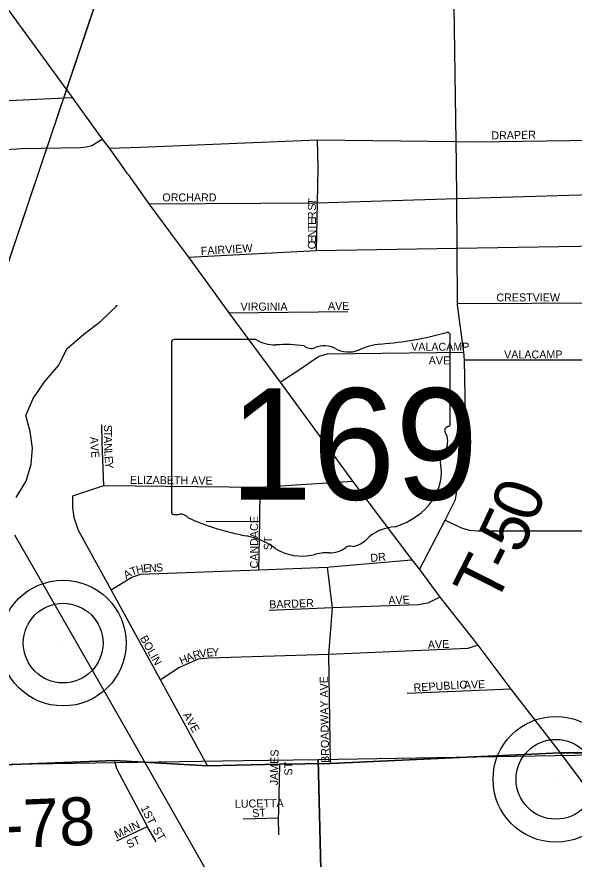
# Model space of a CAD drawing. Extents: x -37878.7 to -37844.7, y -19791.4 to -19769.4.
# Drawn here: x -37874.132 to -37873.473, y -19774.18 to -19773.183 of the extents above; entities that cross this region are included whole.
import ezdxf

# ---------------------------------------------------------------- set-up
doc = ezdxf.new("R2010")
doc.units = 0
for name, color, linetype in [('Default', 7, 'Continuous'), ('GM_X_City_Street', 7, 'Continuous'), ('GM_X_County_Road', 7, 'Continuous'), ('GM_X_County_Road_Text', 7, 'Continuous'), ('GM_X_Minor_River', 7, 'Continuous'), ('GM_X_Rail_Line', 7, 'Continuous'), ('GM_X_Section', 7, 'Continuous'), ('GM_X_State_Route', 7, 'Continuous'), ('GM_X_State_Shield', 7, 'Continuous'), ('GM_X_Township', 7, 'Continuous'), ('GM_X_Township_Road', 7, 'Continuous'), ('GM_X_Township_Road_Text', 7, 'Continuous'), ('GM_X_Township_Subdivision', 7, 'Continuous'), ('GM_X_Township_Subdivision_Text', 7, 'Continuous'), ('GM_X_Unincorporated', 7, 'Continuous'), ('TX_P_1', 7, 'Continuous')]:
    doc.layers.add(name, color=color, linetype=linetype)

msp = doc.modelspace()

# ---------------------------------------------------------------- linework, layer by layer
at = {"layer": 'Default'}
for p, q in [((-37874.07729, -19773.92383), (-37874.07729, -19773.92383)), ((-37873.49453, -19774.08503), (-37873.49453, -19774.08503))]:
    msp.add_line(p, q, dxfattribs=at)
at = {"layer": 'GM_X_City_Street'}
for points in [[(-37873.61204, -19773.35759), (-37873.61271, -19773.3304), (-37873.61542, -19773.1426), (-37873.61632, -19773.11857), (-37873.61725, -19773.09393), (-37873.61692, -19773.08252), (-37873.59457, -19773.0418), (-37873.58297, -19773.02513)], [(-37874.3297, -19773.21439), (-37874.32568, -19773.23387), (-37874.30662, -19773.27977), (-37874.30326, -19773.28503), (-37874.29938, -19773.28668), (-37874.29486, -19773.28661), (-37874.27396, -19773.2877), (-37874.26525, -19773.28737), (-37874.23344, -19773.28615), (-37874.205, -19773.2862), (-37874.14102, -19773.28178), (-37874.06671, -19773.27843)], [(-37874.205, -19773.2862), (-37874.20469, -19773.30441), (-37874.20247, -19773.32293), (-37874.20006, -19773.33471), (-37874.19902, -19773.33782), (-37874.19626, -19773.34058), (-37874.19282, -19773.34179), (-37874.18126, -19773.34224), (-37874.12653, -19773.33856), (-37874.05691, -19773.33742), (-37874.05005, -19773.33677), (-37874.04318, -19773.33497), (-37874.03126, -19773.32761)], [(-37874.02292, -19773.33824), (-37873.98583, -19773.3371), (-37873.77669, -19773.32839), (-37873.61271, -19773.3304), (-37873.58959, -19773.33068)], [(-37873.77568, -19773.36182), (-37873.77669, -19773.32839)]]:
    msp.add_lwpolyline(points, dxfattribs=at)
at = {"layer": 'GM_X_County_Road'}
for points in [[(-37873.48951, -19774.05375), (-37873.48951, -19774.05375), (-37873.43906, -19774.05375), (-37873.321, -19774.05101), (-37873.29591, -19774.0514), (-37873.22557, -19774.05028), (-37873.08696, -19774.04763), (-37873.07008, -19774.04829), (-37872.94239, -19774.04564), (-37872.88479, -19774.04389)], [(-37874.41791, -19774.07867), (-37874.01664, -19774.06271), (-37873.90676, -19774.06892), (-37873.82094, -19774.06728), (-37873.76132, -19774.06615), (-37873.48951, -19774.05375)]]:
    msp.add_lwpolyline(points, dxfattribs=at)
at = {"layer": 'GM_X_Minor_River'}
msp.add_lwpolyline([(-37874.13273, -19773.75141), (-37874.12101, -19773.73218), (-37874.11499, -19773.71231), (-37874.11349, -19773.6933), (-37874.11617, -19773.67361), (-37874.1215, -19773.65437), (-37874.11282, -19773.63444), (-37874.09922, -19773.61479), (-37874.0822, -19773.59506), (-37874.07276, -19773.5755), (-37874.05266, -19773.55837), (-37874.03252, -19773.54313), (-37874.01321, -19773.52449), (-37874.0151, -19773.52491)], dxfattribs=at)
at = {"layer": 'GM_X_Rail_Line'}
msp.add_lwpolyline([(-37873.89745, -19774.21119), (-37873.94617, -19774.12586), (-37873.9926, -19774.04395), (-37874.07139, -19773.90598), (-37874.13433, -19773.79612)], dxfattribs=at)
at = {"layer": 'GM_X_Section'}
for points in [[(-37872.18692, -19774.08978), (-37872.17025, -19774.67952), (-37872.58024, -19774.69042), (-37872.96634, -19774.70069), (-37873.29687, -19774.70587), (-37873.69019, -19774.71163), (-37873.75987, -19774.71265), (-37873.7756, -19774.06152), (-37873.05223, -19774.04922), (-37872.2676, -19774.03426)], [(-37875.12744, -19774.70629), (-37875.12907, -19774.61529), (-37875.13888, -19774.08276), (-37873.86391, -19774.06277), (-37873.7756, -19774.06152), (-37873.75987, -19774.71265), (-37874.06642, -19774.71683), (-37874.13103, -19774.71754)]]:
    msp.add_lwpolyline(points, dxfattribs=at)
at = {"layer": 'GM_X_State_Route'}
for points in [[(-37874.57563, -19772.58079), (-37874.56087, -19772.60126), (-37874.51805, -19772.66009), (-37874.47426, -19772.71957), (-37874.46184, -19772.73656), (-37874.43896, -19772.76827), (-37874.39827, -19772.82366), (-37874.3584, -19772.87955), (-37874.31689, -19772.93478), (-37874.27915, -19772.98707), (-37874.23666, -19773.04525), (-37874.19483, -19773.10293), (-37874.153, -19773.16012), (-37874.06671, -19773.27843), (-37874.03126, -19773.32761), (-37874.02292, -19773.33824), (-37874.00537, -19773.36273)], [(-37874.00537, -19773.36273), (-37874.00182, -19773.36767), (-37874.00053, -19773.36948), (-37873.97578, -19773.40402), (-37873.95248, -19773.43587)], [(-37873.95248, -19773.43587), (-37873.95162, -19773.43705), (-37873.92896, -19773.46717), (-37873.88141, -19773.53302), (-37873.82083, -19773.61513), (-37873.73521, -19773.73227), (-37873.66482, -19773.82552), (-37873.65587, -19773.8369), (-37873.63173, -19773.86938), (-37873.58708, -19773.92637), (-37873.54786, -19773.97819), (-37873.48951, -19774.05375), (-37873.46508, -19774.08632), (-37873.39994, -19774.17562), (-37873.33244, -19774.26754), (-37873.29909, -19774.31219), (-37873.26468, -19774.35921), (-37873.23106, -19774.40478), (-37873.19745, -19774.45126), (-37873.12863, -19774.54293), (-37873.06297, -19774.63485), (-37873.04491, -19774.65944)]]:
    msp.add_lwpolyline(points, dxfattribs=at)
at = {"layer": 'GM_X_State_Shield'}
for p, q in [((-37873.61964, -19773.66439), (-37873.61964, -19773.55971)), ((-37873.94922, -19773.56811), (-37873.94922, -19773.76823)), ((-37873.84945, -19773.56467), (-37873.94597, -19773.56467)), ((-37873.61967, -19773.66437), (-37873.61964, -19773.66439))]:
    msp.add_line(p, q, dxfattribs=at)
for centre, major_axis, start_param, end_param in [((-37873.73704, -19773.29183), (0.34952, 0), 4.814394, 5.042369), ((-37873.62329, -19773.55927), (0.00367, 0), 6.141152, 7.989035), ((-37873.94544, -19773.56768), (0.00382, 0), 1.712693, 3.28349), ((-37873.82647, -19773.54143), (0.03703, 0), 4.042523, 4.731795), ((-37873.81419, -19773.67701), (0.13295, 0), 1.404758, 1.657858), ((-37873.78401, -19773.56664), (0.01068, 0), 3.836095, 5.185415), ((-37873.76832, -19773.58977), (0.02221, 0), 0.950623, 2.079405), ((-37873.69246, -19773.62579), (0.07032, 0), 1.699011, 2.107814), ((-37873.73965, -19773.55805), (0.02672, 0), 4.081561, 5.145723), ((-37873.62049, -19773.67208), (0.00568, 0), 1.883978, 3.671073), ((-37873.62355, -19773.6648), (0.00393, 0), 5.05454, 6.418171), ((-37873.65661, -19773.68531), (0.03409, 0), 5.934695, 6.695948), ((-37873.60649, -19773.7082), (0.0248, 0), 2.387724, 3.262537), ((-37873.71746, -19773.72152), (0.08742, 0), 5.101752, 6.440018), ((-37873.94541, -19773.76867), (0.00385, 0), 3.00124, 4.508301), ((-37873.94483, -19773.74819), (0.0294, 0), 4.665946, 4.897461), ((-37873.93881, -19773.77977), (0.0106, 0), 0.519207, 1.627899), ((-37873.80499, -19773.59997), (0.2524, 0), 4.195997, 4.488961), ((-37873.6806, -19773.82441), (0.04788, 0), 1.647645, 2.488434), ((-37873.88024, -19773.85813), (0.07897, 0), 0.823519, 1.323587), ((-37873.74126, -19773.78762), (0.02824, 0), 4.937069, 5.64225), ((-37873.79482, -19773.78077), (0.05011, 0), 4.026481, 4.996735), ((-37873.76221, -19773.79575), (0.0267, 0), 4.691044, 5.507374), ((-37873.73806, -19773.81513), (0.00752, 0), 1.147584, 2.315152), ((-37873.76587, -19773.84996), (0.04118, 0), 1.495662, 1.94098)]:
    msp.add_ellipse(centre, major_axis=major_axis, ratio=0.8, start_param=start_param, end_param=end_param, dxfattribs=at)
at = {"layer": 'GM_X_Township'}
for points in [[(-37872.2676, -19774.0341), (-37872.38016, -19774.03604), (-37872.76408, -19774.04266), (-37872.85506, -19774.043), (-37872.94239, -19774.04564), (-37873.07009, -19774.04829), (-37873.08696, -19774.04763), (-37873.22557, -19774.05027), (-37873.2959, -19774.0514), (-37873.32101, -19774.05101), (-37873.43906, -19774.05375), (-37873.48951, -19774.05375), (-37873.76133, -19774.06615), (-37873.82094, -19774.06728), (-37873.90676, -19774.06892), (-37874.01664, -19774.06271), (-37874.41791, -19774.07867), (-37875.13726, -19774.08233), (-37875.16478, -19772.49865)], [(-37875.12559, -19774.70629), (-37875.12978, -19774.45993), (-37875.13234, -19774.33027), (-37875.13726, -19774.08233), (-37874.41791, -19774.07867), (-37874.01664, -19774.06271), (-37873.90676, -19774.06892), (-37873.82094, -19774.06728), (-37873.76133, -19774.06615), (-37873.48951, -19774.05375), (-37873.43906, -19774.05375), (-37873.32101, -19774.05101), (-37873.2959, -19774.0514), (-37873.22557, -19774.05027), (-37873.08696, -19774.04763), (-37873.07009, -19774.04829), (-37872.94239, -19774.04564), (-37872.85506, -19774.043), (-37872.76408, -19774.04266), (-37872.38016, -19774.03604), (-37872.2676, -19774.0341)]]:
    msp.add_lwpolyline(points, dxfattribs=at)
at = {"layer": 'GM_X_Township_Road'}
msp.add_lwpolyline([(-37873.65587, -19773.8369), (-37873.62542, -19773.77824), (-37873.61335, -19773.75381), (-37873.61136, -19773.74185), (-37873.60047, -19773.71835), (-37873.60284, -19773.58861), (-37873.60336, -19773.57968), (-37873.61103, -19773.52358), (-37873.61104, -19773.52206), (-37873.61144, -19773.45655), (-37873.61179, -19773.39791), (-37873.61204, -19773.35759)], dxfattribs=at)
at = {"layer": 'GM_X_Township_Subdivision'}
for points in [[(-37873.58959, -19773.33068), (-37873.31103, -19773.32681), (-37873.24179, -19773.32585)], [(-37873.77763, -19773.45923), (-37873.7765, -19773.40279), (-37873.77568, -19773.36182)], [(-37873.97578, -19773.40402), (-37873.7765, -19773.40279), (-37873.61179, -19773.39791), (-37873.34641, -19773.39006), (-37873.31379, -19773.38909)], [(-37873.92896, -19773.46717), (-37873.77763, -19773.45923), (-37873.61144, -19773.45655), (-37873.34641, -19773.45227), (-37873.31127, -19773.45171), (-37873.28126, -19773.45122)], [(-37873.61104, -19773.52206), (-37873.34564, -19773.52088), (-37873.28936, -19773.52033)], [(-37873.88141, -19773.53302), (-37873.74063, -19773.53138)], [(-37873.60284, -19773.58861), (-37873.23709, -19773.58883), (-37873.09979, -19773.58392), (-37872.66782, -19773.57005)], [(-37873.82083, -19773.61513), (-37873.79431, -19773.5978), (-37873.78249, -19773.5894), (-37873.77434, -19773.58441), (-37873.76462, -19773.58178), (-37873.60336, -19773.57968)], [(-37874.02918, -19773.7372), (-37874.03115, -19773.68652), (-37874.0317, -19773.66568)], [(-37874.06593, -19773.7497), (-37874.02918, -19773.7372), (-37873.84424, -19773.73923), (-37873.73521, -19773.73227)], [(-37873.84569, -19773.83705), (-37873.84484, -19773.77975), (-37873.84424, -19773.73923)], [(-37873.90676, -19774.06892), (-37873.96224, -19773.96747), (-37874.02053, -19773.8609), (-37874.05894, -19773.79068), (-37874.06431, -19773.77513), (-37874.06588, -19773.76337), (-37874.06593, -19773.7497)], [(-37873.90821, -19773.77997), (-37873.84484, -19773.77975)], [(-37873.62542, -19773.77824), (-37873.60546, -19773.78795), (-37873.5968, -19773.79032), (-37873.58708, -19773.79084), (-37873.4547, -19773.79115), (-37873.45282, -19773.7911), (-37873.33687, -19773.79025), (-37873.239, -19773.78953)], [(-37874.02053, -19773.8609), (-37873.99683, -19773.84629), (-37873.98583, -19773.84246), (-37873.84569, -19773.83705), (-37873.76487, -19773.83393), (-37873.76142, -19773.8338), (-37873.66482, -19773.82552)], [(-37873.76132, -19774.06615), (-37873.76329, -19773.93718), (-37873.75884, -19773.88225), (-37873.76487, -19773.83393)], [(-37873.63173, -19773.86938), (-37873.64617, -19773.87647), (-37873.65747, -19773.87857), (-37873.75884, -19773.88225), (-37873.83376, -19773.88527)], [(-37873.58708, -19773.92637), (-37873.5989, -19773.93031), (-37873.76329, -19773.93718), (-37873.90533, -19773.94166), (-37873.91748, -19773.94284), (-37873.93985, -19773.95278), (-37873.96224, -19773.96747)], [(-37873.54786, -19773.97819), (-37873.67047, -19773.98346)], [(-37873.97694, -19774.14199), (-37873.97754, -19774.14092), (-37874.01364, -19774.07256), (-37874.01664, -19774.06271)], [(-37873.82237, -19774.12293), (-37873.82237, -19774.12286), (-37873.82094, -19774.06728)], [(-37873.82221, -19774.15076), (-37873.82258, -19774.1312), (-37873.82237, -19774.12293)], [(-37874.01392, -19774.1578), (-37873.97754, -19774.14092)], [(-37873.82258, -19774.1312), (-37873.86436, -19774.13209)], [(-37873.96728, -19774.1592), (-37873.97694, -19774.14199)]]:
    msp.add_lwpolyline(points, dxfattribs=at)
at = {"layer": 'GM_X_Unincorporated'}
for centre, radius in [((-37874.07729, -19773.92383), 0.0744), ((-37874.07729, -19773.92383), 0.04716), ((-37873.49453, -19774.08503), 0.0744), ((-37873.49453, -19774.08503), 0.04716)]:
    msp.add_circle(centre, radius, dxfattribs=at)
at = {"layer": 'TX_P_1'}
msp.add_line((-37874.34571, -19774.07578), (-37873.99118, -19773.02513), dxfattribs=at)
msp.add_lwpolyline([(-37874.34571, -19774.07578), (-37874.24497, -19773.02513), (-37873.99118, -19773.02513)], close=True, dxfattribs=at)

# ---------------------------------------------------------------- texts
at = {"layer": 'Default'}
for s in ['s', 'r']:
    msp.add_text(s, height=0.000189, dxfattribs=at).set_placement((-37873.78813, -19773.68147))
msp.add_text('169', height=0.000189, rotation=0.00001, dxfattribs=at).set_placement((-37873.85499, -19773.69525))
at = {"layer": 'GM_X_County_Road_Text'}
msp.add_text('C-78', height=0.056818, rotation=2.40021, dxfattribs=at).set_placement((-37874.20335, -19774.16916))
at = {"layer": 'GM_X_State_Shield'}
msp.add_text('169', height=0.131836, dxfattribs=at).set_placement((-37873.88053, -19773.75412))
at = {"layer": 'GM_X_Township_Road_Text'}
for s, rotation, p in [('0', 70.21318, (-37873.51964, -19773.78334)), ('5', 64.95869, (-37873.53662, -19773.8203)), ('-', 63.56497, (-37873.54767, -19773.84255)), ('T', 63.23753, (-37873.56696, -19773.88082))]:
    msp.add_text(s, height=0.05682, rotation=rotation, dxfattribs=at).set_placement(p)
at = {"layer": 'GM_X_Township_Subdivision_Text'}
for s, height, rotation, p in [('DRAPER', 0.00947, 1.04105, (-37873.57086, -19773.32792)), ('ORCHARD', 0.00947, 0.00001, (-37873.95999, -19773.40126)), ('T', 0.00947, 86.39127, (-37873.7783, -19773.40569)), ('S', 0.00947, 89.83605, (-37873.77832, -19773.41221)), ('E', 0.00947, 89.83605, (-37873.77836, -19773.42888)), ('R', 0.00947, 89.84555, (-37873.77834, -19773.42221)), ('T', 0.00947, 89.85062, (-37873.77838, -19773.43554)), ('E', 0.00947, 89.83605, (-37873.77842, -19773.45054)), ('N', 0.00947, 89.84623, (-37873.7784, -19773.44388)), ('FAIRVIEW', 0.00947, 3.36778, (-37873.91426, -19773.46459)), ('C', 0.00947, 89.85429, (-37873.77844, -19773.45804)), ('CRESTVIEW', 0.00947, 0.00001, (-37873.56499, -19773.51959)), ('VIRGINIA', 0.00947, 0.00001, (-37873.86749, -19773.53042)), ('AVE', 0.00947, 0.00001, (-37873.76416, -19773.52959)), ('VALACAMP', 0.00947, 0.00001, (-37873.66583, -19773.57792)), ('VALACAMP', 0.00947, 0.00001, (-37873.55583, -19773.58709)), ('AVE', 0.00947, 0.00001, (-37873.64499, -19773.59421)), ('S', 0.00947, 270.05466, (-37874.02904, -19773.66554)), ('T', 0.00947, 270.02733, (-37874.02904, -19773.6722)), ('A', 0.00947, 271.72678, (-37874.04533, -19773.67978)), ('A', 0.00947, 270.69119, (-37874.02903, -19773.67899)), ('V', 0.00947, 274.61515, (-37874.04505, -19773.68863)), ('N', 0.00947, 272.66531, (-37874.02892, -19773.68768)), ('E', 0.00947, 275.3887, (-37874.04437, -19773.69707)), ('L', 0.00947, 273.0167, (-37874.02853, -19773.69607)), ('E', 0.00947, 273.0167, (-37874.02818, -19773.70272)), ('Y', 0.00947, 273.02621, (-37874.02783, -19773.70938)), ('ELIZABETH AVE', 0.0094696, 359.46978, (-37873.99831, -19773.73542)), ('CANDACE', 0.00947, 90, (-37873.84677, -19773.83553)), ('ST', 0.00947, 90, (-37873.83048, -19773.81387)), ('DR', 0.00947, 6.00541, (-37873.71351, -19773.82793)), ('H', 0.00947, 11.84138, (-37873.99007, -19773.84205)), ('E', 0.00947, 4.73188, (-37873.98222, -19773.84038)), ('N', 0.00947, 3.26955, (-37873.97564, -19773.83983)), ('S', 0.00947, 3.26694, (-37873.96732, -19773.83936)), ('A', 0.00947, 29.69472, (-37874.00279, -19773.84831)), ('T', 0.00947, 21.21797, (-37873.99589, -19773.84434)), ('BARDER', 0.00947, 2.0443, (-37873.83339, -19773.88292)), ('AVE', 0.00947, 1.97389, (-37873.69255, -19773.87792)), ('BOLIN', 0.00947, 299.051, (-37873.98677, -19773.918)), ('AVE', 0.00947, 1.97766, (-37873.64589, -19773.93042)), ('V', 0.00947, 8.63234, (-37873.91547, -19773.94119)), ('E', 0.00947, 4.8952, (-37873.90739, -19773.93996)), ('Y', 0.00947, 3.46592, (-37873.90081, -19773.93939)), ('H', 0.00947, 22.67198, (-37873.9374, -19773.94975)), ('A', 0.00947, 22.67198, (-37873.92971, -19773.94654)), ('R', 0.00947, 17.85521, (-37873.92222, -19773.9434)), ('BROADWAY AVE', 0.0094696, 91.00454, (-37873.76261, -19774.06556)), ('REPUBLIC', 0.00947, 3.41627, (-37873.6626, -19773.98125)), ('AVE', 0.00947, 1.97389, (-37873.60339, -19773.97792)), ('AVE', 0.00947, 299.2491, (-37873.93594, -19774.00883)), ('JAMES', 0.00947, 88.66346, (-37873.82344, -19774.09216)), ('ST', 0.00947, 90, (-37873.80631, -19774.08053)), ('LUCETTA', 0.00947, 0.91062, (-37873.87415, -19774.11875)), ('1ST', 0.00947, 296.56069, (-37873.98589, -19774.1189)), ('ST', 0.00947, 3.58144, (-37873.85341, -19774.13002)), ('MAIN', 0.00947, 25.19926, (-37874.01408, -19774.15559)), ('ST', 0.00947, 299.74321, (-37873.97178, -19774.14465)), ('ST', 0.00947, 25.01769, (-37873.99969, -19774.16701))]:
    msp.add_text(s, height=height, rotation=rotation, dxfattribs=at).set_placement(p)

doc.saveas('drawing.dxf')
